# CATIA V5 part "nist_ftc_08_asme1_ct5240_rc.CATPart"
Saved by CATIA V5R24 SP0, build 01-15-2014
Part number: NIST PMI FTC 08 ASME1
Revision: C
Description: NIST PMI test model downloaded from http://go.usa.gov/mGVm
Bounding box of the stored display mesh (mm): x -155.797 to 155.797, y -111.347 to 111.347, z 0 to 48.26
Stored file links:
  C:\work\NIST\DCC_review\nist_ftc_08_asme1_ct5240_rc.CATPart
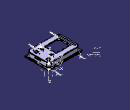
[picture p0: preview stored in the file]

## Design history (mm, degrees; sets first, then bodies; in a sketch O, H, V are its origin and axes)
f4a2d38f3ddc11d3a929006094b99c4b_11 "CATTPSSet"
TTRSSet1
Set1 "MBD_A_GEOM"
  Plane1: type Equation, A 0.57735, B -0.57735, C -0.57735, Length -28.26, RefPoint vertex [face of Fillet7 | start face of Pad1 | face of Pad1 from Sketch5.L4], RefAxis AxisSystem9
Set2
  Point1: type Center, Curve edge [face of Hole1 | start face of Pad1]
  Point2: type OnPlane, Support end face of Pad2, H 142.875, V 98.425, Direction (1, 0, 0)
  Point3: type Center, Curve edge [end face of Pad2 | face of Hole5]
Set3 "MBD_A"
  AxisSystem1 "ABC": origin (142.875, 98.425, 0), X (0, -1, 0), Y (-1, 0, 0), Z (0, 0, -1)
  AxisSystem2 "DBC": origin (142.875, 98.425, 48.26), X (0, 1, 0), Y (-1, 0, 0), Z (0, 0, 1)
Set4 "MBD_B"
  AxisSystem3: origin (142.875, 98.425, 0), X (0, -1, 0), Y (-1, 0, 0), Z (0, 0, -1)
  AxisSystem4: origin (142.875, 98.425, 48.26), X (0, 1, 0), Y (-1, 0, 0), Z (0, 0, 1)
  Sketch1 on face of Pad2 from Sketch6.L3, origin (0, -102.4573, 0), H (1, 0, 0), V (0, 0, 1)
    axis line L1 (0, -16.144) -> (0, 81.9836)
    point P5 (0, -16.144)
    line L2 (50.8, 45.212) -> (50.8, 11.684)
    line L3 (-50.8, 45.212) -> (-50.8, 11.684)
    projected line E4 (121.8957, 11.684) -> (-121.8957, 11.684) from edge [face of Pad2 from Sketch6.L3 | face of Fillet9]
    projected line E5 (50.8, 11.684) -> (-50.8, 11.684) from edge [face of Pad2 from Sketch6.L3 | face of Fillet9]
    distance L1 L2 = 50.8
    distance L1 L3 = 50.8
    coincidence: P5 V
    vertical: L1 V, L2 V, L3 V
  AxisSystem5 "DE-F": origin (-38.1, 0, 48.26), X (0, 1, 0), Y (-1, 0, 0), Z (0, 0, 1)
  Sketch2 on end face of Pad2, origin (0, 0, 48.26), H (1, 0, 0), V (0, 1, 0)
    axis line L1 (-38.1, 55.626) -> (-38.1, -55.626)
    point P1 (-38.1, -55.626)
    point P2 (-38.1, 55.626)
    reference projected point E3 (-38.1, -55.626) from axis of face of RectPattern3
    reference projected point E4 (-38.1, 55.626) from axis of face of RectPattern3
    point P3 (-38.1, 0)
    vertical: L1 V
    coincidence: E3 P1, E4 P2
    midpoint: P3 L1
  Fill1: Boundary Sketch1
Set5 "MBD_C"
  Sketch3 on end face of Pad2, origin (0, 0, 48.26), H (1, 0, 0), V (0, 1, 0)
    axis line L1 (109.22, -20.955) -> (109.22, -78.105)
    point P1 (109.22, -20.955)
    point P2 (109.22, -78.105)
    reference projected point E1 (109.22, -20.955) from axis of face of Hole4
    reference projected point E2 (109.22, -78.105) from axis of face of RectPattern4
    point P3 (109.22, -49.53)
    vertical: L1 V
    coincidence: E1 P1, E2 P2
    midpoint: P3 L1
  AxisSystem6 "DG": origin (109.22, -49.53, 48.26), X (0, 1, 0), Y (-1, 0, 0), Z (0, 0, 1)
  AxisSystem7: origin (142.875, 98.425, 48.26), X (0, 1, 0), Y (-1, 0, 0), Z (0, 0, 1)
Set6 "MBD_D"
  Sketch4 on end face of Pad2, origin (0, 0, 48.26), H (1, 0, 0), V (0, 1, 0)
    axis line L1 (69.85, -25.1263) -> (69.85, -67.31)
    point P2 (69.85, -67.31)
    reference projected point E1 (69.85, -67.31) from axis of face of RectPattern5
    point P3 (69.85, -46.2182)
    vertical: L1 V
    coincidence: E1 P2
    midpoint: P3 L1
  AxisSystem8 "DHJ": origin (69.85, -46.2182, 48.26), X (0, 1, 0), Y (-1, 0, 0), Z (0, 0, 1)
  AxisSystem9 "DKL": origin (69.85, 25.4, 48.26), X (0, 1, 0), Y (-1, 0, 0), Z (0, 0, 1)
  AxisSystem10: origin (142.875, 98.425, 48.26), X (0, 1, 0), Y (-1, 0, 0), Z (0, 0, 1)
Body1 (main body)
  Sketch5 on xy-plane, origin (0, 0, 0), H (1, 0, 0), V (0, 1, 0)
    line L1 (-155.7973, 111.3473) -> (155.7973, 111.3473)
    line L2 (155.7973, 111.3473) -> (155.7973, -111.3473)
    line L3 (155.7973, -111.3473) -> (-155.7973, -111.3473)
    line L4 (-155.7973, -111.3473) -> (-155.7973, 111.3473)
    length L3 = 311.5945
    distance V L4 = 155.7973
    length L2 = 222.6945
    distance H L1 = 111.3473
    horizontal: L1 H, L3 H
    vertical: L2 V, L4 V
  Pad1: profile Sketch5, direction (0, 0, 1), length 10.16
  Sketch6 on end face of Pad1, origin (0, 0, 10.16), H (1, 0, 0), V (0, 1, 0)
    line L1 (-123.1583, 102.4573) -> (123.1583, 102.4573)
    line L2 (146.0183, 79.5973) -> (146.0183, -79.5973)
    line L3 (123.1583, -102.4573) -> (-123.1583, -102.4573)
    line L4 (-146.0183, -79.5973) -> (-146.0183, 79.5973)
    line L5 (123.1583, 102.4573) -> (146.0183, 79.5973)
    line L6 (146.0183, -79.5973) -> (123.1583, -102.4573)
    line L7 (-123.1583, 102.4573) -> (-146.0183, 79.5973)
    point P1 (-142.7555, 82.86)
    line L8 (-146.0183, -79.5973) -> (-123.1583, -102.4573)
    point P2 (-123.1583, 102.4573)
    point P5 (-123.1583, -102.4573)
    point P6 (123.1583, -102.4573)
    point P9 (123.1583, 102.4573)
    reference projected line E1 (-155.7973, 111.3473) -> (-155.7973, -111.3473) from edge [face of Pad1 from Sketch5.L4 | end face of Pad1]
    reference projected line E2 (155.7973, -111.3473) -> (155.7973, 111.3473) from edge [face of Pad1 from Sketch5.L2 | end face of Pad1]
    reference projected line E3 (-155.7973, -111.3473) -> (155.7973, -111.3473) from edge [face of Pad1 from Sketch5.L3 | end face of Pad1]
    reference projected line E4 (155.7973, 111.3473) -> (-155.7973, 111.3473) from edge [face of Pad1 from Sketch5.L1 | end face of Pad1]
    angle L1 L7 = 45
    distance L4 E1 = 9.779
    distance L2 E2 = 9.779
    distance L3 E3 = 8.89
    distance E4 L1 = 8.89
    distance L4 P2 = 22.86
    distance P9 L2 = 22.86
    angle L5 L1 = 45
    distance L2 P6 = 22.86
    angle L3 L6 = 45
    distance P5 L4 = 22.86
    angle L3 L8 = 45
    horizontal: L1 H, L3 H
    vertical: L2 V, L4 V
    coincidence: P1 L7
  Pad2: profile Sketch6, direction (0, 0, 1), length 38.1
  Sketch7 on end face of Pad1, origin (138.8883, 98.2031, 10.16), H (1, 0, 0), V (0, 1, 0)
    point P1 (3.9867, 0.2219)
    reference intersected line E1 through (0, -98.2031) direction (-1, 0) from zx-plane
    reference intersected line E2 through (-138.8883, 0) direction (0, 1) from yz-plane
    distance E1 P1 = 98.425
    distance E2 P1 = 142.875
  Hole1: placed by Sketch7, at (142.875, 98.425, 10.16) direction (0, 0, -1), diameter 6.0325, through (limit type 6)
  RectPattern1: of Hole1, direction 1 instances 2, spacing 285.75, along edge [face of Pad1 from Sketch5.L1 | end face of Pad1], direction 2 instances 2, spacing 196.85, along edge [face of Pad1 from Sketch5.L2 | end face of Pad1] reversed
  Sketch8 on start face of Pad1, origin (0, 0, 0), H (1, 0, 0), V (0, -1, 0)
    line L1 (120.528, 96.1073) -> (139.6683, 76.967)
    line L2 (139.6683, 76.967) -> (139.6683, -76.967)
    line L3 (139.6683, -76.967) -> (120.528, -96.1073)
    line L4 (120.528, -96.1073) -> (-120.528, -96.1073)
    line L5 (-120.528, -96.1073) -> (-139.6683, -76.967)
    line L6 (-139.6683, -76.967) -> (-139.6683, 76.967)
    line L7 (-139.6683, 76.967) -> (-120.528, 96.1073)
    line L8 (-120.528, 96.1073) -> (120.528, 96.1073)
  Pocket1: profile Sketch8, direction (0, 0, 1), length 44.831
  Sketch9 on end face of Pad2, origin (0, 0, 48.26), H (1, 0, 0), V (0, 1, 0)
    point P1 (-107.95, 57.15)
    line L1 (-107.95, 57.15) -> (-90.17, 57.15)
    line L2 (31.75, 57.15) -> (31.75, 33.02)
    line L3 (31.75, -57.15) -> (13.97, -57.15)
    line L4 (-107.95, -57.15) -> (-107.95, -33.02)
    point P3 (31.75, -57.15)
    point P4 (-107.95, -57.15)
    reference intersected line E1 through (0, 0) direction (0, 1) from yz-plane
    reference intersected line E2 through (0, 0) direction (-1, 0) from zx-plane
    arc A1 centre (-106.426, 25.4) radius 7.62 from (-106.426, 17.78) to (-106.426, 33.02) ccw
    point P5 (-106.426, 25.4)
    reference intersected line E3 through (0, 0) direction (-1, 0) from zx-plane
    line L5 (-106.426, 33.02) -> (-107.95, 33.02)
    point P6 (-106.426, 33.02)
    line L6 (-106.426, 17.78) -> (-107.95, 17.78)
    point P7 (-106.426, 17.78)
    point P8 (-107.95, 33.02)
    line L7 (-107.95, 33.02) -> (-107.95, 57.15)
    point P9 (-107.95, 17.78)
    construction line L8 (0, 0) -> (-140, 0)
    point P11 (-107.95, -33.02)
    point P12 (-106.426, -33.02)
    line L9 (-106.426, -33.02) -> (-107.95, -33.02)
    point P13 (-106.426, -17.78)
    arc A2 centre (-106.426, -25.4) radius 7.62 from (-106.426, -17.78) to (-106.426, -33.02) cw
    point P15 (-107.95, -17.78)
    line L10 (-106.426, -17.78) -> (-107.95, -17.78)
    line L11 (-107.95, -17.78) -> (-107.95, 17.78)
    axis line L12 (-38.1, -57.15) -> (-38.1, 57.15)
    point P16 (-38.1, -57.15)
    point P17 (-38.1, 57.15)
    point P18 (30.226, 33.02)
    point P19 (30.226, 17.78)
    arc A3 centre (30.226, 25.4) radius 7.62 from (30.226, 17.78) to (30.226, 33.02) cw
    point P21 (31.75, 17.78)
    line L13 (30.226, 17.78) -> (31.75, 17.78)
    point P22 (31.75, 33.02)
    line L14 (30.226, 33.02) -> (31.75, 33.02)
    point P23 (31.75, -17.78)
    point P24 (30.226, -17.78)
    line L15 (30.226, -17.78) -> (31.75, -17.78)
    point P25 (30.226, -33.02)
    arc A4 centre (30.226, -25.4) radius 7.62 from (30.226, -17.78) to (30.226, -33.02) ccw
    point P27 (31.75, -33.02)
    line L16 (30.226, -33.02) -> (31.75, -33.02)
    line L17 (31.75, 17.78) -> (31.75, -17.78)
    line L18 (31.75, -33.02) -> (31.75, -57.15)
    arc A5 centre (6.35, -55.626) radius 7.62 from (13.97, -55.626) to (-1.27, -55.626) ccw
    point P28 (6.35, -55.626)
    line L19 (13.97, -55.626) -> (13.97, -57.15)
    point P29 (13.97, -55.626)
    line L20 (-1.27, -55.626) -> (-1.27, -57.15)
    point P30 (-1.27, -55.626)
    line L21 (-1.27, -57.15) -> (-30.48, -57.15)
    point P32 (-1.27, -57.15)
    point P33 (-74.93, -57.15)
    point P34 (-74.93, -55.626)
    line L22 (-74.93, -55.626) -> (-74.93, -57.15)
    point P35 (-90.17, -57.15)
    point P36 (-90.17, -55.626)
    line L23 (-90.17, -55.626) -> (-90.17, -57.15)
    arc A6 centre (-82.55, -55.626) radius 7.62 from (-90.17, -55.626) to (-74.93, -55.626) cw
    line L24 (-90.17, -57.15) -> (-107.95, -57.15)
    point P38 (-90.17, 57.15)
    point P39 (-90.17, 55.626)
    line L25 (-90.17, 55.626) -> (-90.17, 57.15)
    point P40 (-74.93, 55.626)
    arc A7 centre (-82.55, 55.626) radius 7.62 from (-90.17, 55.626) to (-74.93, 55.626) ccw
    point P42 (-74.93, 57.15)
    line L26 (-74.93, 55.626) -> (-74.93, 57.15)
    point P43 (-1.27, 57.15)
    point P44 (-1.27, 55.626)
    line L27 (-1.27, 55.626) -> (-1.27, 57.15)
    point P45 (13.97, 55.626)
    arc A8 centre (6.35, 55.626) radius 7.62 from (13.97, 55.626) to (-1.27, 55.626) cw
    line L28 (13.97, 55.626) -> (13.97, 57.15)
    line L29 (13.97, 57.15) -> (31.75, 57.15)
    line L30 (-74.93, 57.15) -> (-45.72, 57.15)
    arc A9 centre (-38.1, -55.626) radius 7.62 from (-30.48, -55.626) to (-45.72, -55.626) ccw
    point P48 (-38.1, -55.626)
    line L31 (-30.48, -55.626) -> (-30.48, -57.15)
    point P49 (-30.48, -55.626)
    line L32 (-45.72, -55.626) -> (-45.72, -57.15)
    point P50 (-45.72, -55.626)
    line L33 (-45.72, -57.15) -> (-74.93, -57.15)
    point P51 (-30.48, -57.15)
    point P52 (-45.72, -57.15)
    point P53 (-45.72, 57.15)
    point P54 (-45.72, 55.626)
    line L34 (-45.72, 55.626) -> (-45.72, 57.15)
    point P55 (-30.48, 55.626)
    arc A10 centre (-38.1, 55.626) radius 7.62 from (-30.48, 55.626) to (-45.72, 55.626) cw
    point P57 (-30.48, 57.15)
    line L35 (-30.48, 55.626) -> (-30.48, 57.15)
    line L36 (-30.48, 57.15) -> (-1.27, 57.15)
    distance L4 E1 = 107.95
    distance E2 L3 = 57.15
    distance P5 L4 = 1.524
    radius A1 = 7.62
    distance E3 P5 = 25.4
    distance P4 P1 = 114.3
    radius A5 = 7.62
    distance L3 P28 = 1.524
    distance P28 L12 = 44.45
    distance P3 P4 = 139.7
    radius A9 = 7.62
    distance L21 P48 = 1.524
    horizontal: L1 H, L3 H, L5 H, L6 H, L8 H, L21 H, L24 H, L29 H, L30 H, L33 H, L36 H
    vertical: L2 V, L4 V, L7 V, L11 V, L12 V, L17 V, L18 V, L20 V, L19 V, L31 V, L32 V
    tangency: L5 A1, L6 A1, L19 A5, L20 A5, L31 A9, L32 A9
    coincidence: L4 P8, L4 L11, L2 L17, L17 L18, L3 P16, L3 L21, L1 P17, L1 L29, P48 L12, L21 L33, L30 L36
    symmetry: P8 P11 L8, P6 P12 L8, L5 L9 L8, P7 P13 L8, A1 A2 L8, P9 P15 L8, L6 L10 L8, P6 P18 L12, P7 P19 L12, A1 A3 L12, P9 P21 L12, L6 L13 L12, P8 P22 L12, L5 L14 L12, P15 P23 L12, P13 P24 L12, L10 L15 L12, P12 P25 L12, A2 A4 L12, P11 P27 L12, L9 L16 L12, P32 P33 L12, P30 P34 L12, L20 L22 L12, P29 P36 L12, L19 L23 L12, A5 A6 L12, P35 P38 L8, P36 P39 L8, L23 L25 L8, P34 P40 L8, A6 A7 L8, P33 P42 L8, L22 L26 L8, P32 P43 L8, P30 P44 L8, L20 L27 L8, P29 P45 L8, A5 A8 L8, L19 L28 L8, P52 P53 L8, P50 P54 L8, L32 L34 L8, P49 P55 L8, A9 A10 L8, P51 P57 L8, L31 L35 L8
  Pocket2: profile Sketch9, direction (0, 0, -1), through (limit type 6)
  Sketch10 on end face of Pad2, origin (-103.9484, 24.3967, 48.26), H (1, 0, 0), V (0, 1, 0)
    point P1 (-2.4776, 1.0033)
    reference projected arc E1 centre (-2.4776, 1.0033) radius 7.62 from (-2.4776, -6.6167) to (-2.4776, 8.6233) ccw from edge [end face of Pad2 | face of Pocket2 from Sketch9.A1]
    concentricity: E1 P1
  Hole2: placed by Sketch10, at (-106.426, 25.4, 48.26) direction (0, 0, -1), diameter 5.4102, through (limit type 6)
  RectPattern2: of Hole2, direction 1 instances 2, spacing 50.8, along edge [end face of Pad2 | face of Pocket2 from Sketch9.L11], direction 2 instances 2, spacing 136.652, along edge [end face of Pad2 | face of Pocket2 from Sketch9.L21]
  Sketch11 on end face of Pad2, origin (-83.348, -53.7047, 48.26), H (1, 0, 0), V (0, 1, 0)
    point P1 (0.798, -1.9213)
    reference projected point E1 (0.798, -1.9213) from axis of face of Pocket2 from Sketch9.A6
    coincidence: E1 P1
  Hole3: placed by Sketch11, at (-82.55, -55.626, 48.26) direction (0, 0, -1), diameter 5.4102, through (limit type 6)
  RectPattern3: of Hole3, direction 1 instances 3, spacing 44.45, along edge [end face of Pad2 | face of Pocket2 from Sketch9.L33], direction 2 instances 2, spacing 111.252, along edge [end face of Pad2 | face of Pocket2 from Sketch9.L11] reversed
  Sketch12 on end face of Pad2, origin (0, 0, 48.26), H (1, 0, 0), V (0, 1, 0)
    line L1 (95.25, -35.56) -> (123.19, -35.56)
    line L2 (123.19, -35.56) -> (123.19, -63.5)
    line L3 (123.19, -63.5) -> (95.25, -63.5)
    line L4 (95.25, -63.5) -> (95.25, -35.56)
    reference intersected line E1 through (0, 0) direction (0, 1) from yz-plane
    reference intersected line E2 through (0, 0) direction (-1, 0) from zx-plane
    length L1 = 27.94
    length L2 = 27.94
    distance E1 L4 = 95.25
    distance E2 L1 = 35.56
    horizontal: L1 H, L3 H
    vertical: L2 V, L4 V
  Pocket3: profile Sketch12, direction (0, 0, -1), through (limit type 6)
  Sketch13 on end face of Pad2, origin (108.1397, -22.5136, 48.26), H (1, 0, 0), V (0, 1, 0)
    point P1 (1.0803, 1.5586)
    reference intersected line E1 through (-108.1397, 0) direction (0, 1) from yz-plane
    reference intersected line E2 through (0, 22.5136) direction (-1, 0) from zx-plane
    distance E1 P1 = 109.22
    distance E2 P1 = 20.955
  Hole4: placed by Sketch13, at (109.22, -20.955, 48.26) direction (0, 0, -1), diameter 6.35, through (limit type 6)
  RectPattern4: of Hole4, direction 1 instances 2, spacing 57.15, along edge [end face of Pad2 | face of Pocket3 from Sketch12.L2] reversed, direction 2 instances 2, spacing 111.252
  Sketch14 on end face of Pad2, origin (96.9796, 25.3434, 48.26), H (1, 0, 0), V (0, 1, 0)
    point P1 (-27.1296, 0.0566)
    reference intersected line E1 through (-96.9796, 0) direction (0, 1) from yz-plane
    reference intersected line E2 through (0, -25.3434) direction (-1, 0) from zx-plane
    distance E1 P1 = 69.85
    distance P1 E2 = 25.4
  Hole5: placed by Sketch14, at (69.85, 25.4, 48.26) direction (0, 0, -1), diameter 5.7912, through (limit type 6)
  RectPattern5: of Hole5, direction 1 instances 2, spacing 92.71, along edge [face of Pad2 from Sketch6.L2 | end face of Pad2] reversed, direction 2 instances 2, spacing 111.252
  Sketch15 on end face of Pad2, origin (70.1334, 59.5545, 48.26), H (1, 0, 0), V (0, 1, 0)
    point P1 (-0.2834, 7.7555)
    reference intersected line E1 through (0, -59.5545) direction (-1, 0) from zx-plane
    reference intersected line E2 through (-70.1334, 0) direction (0, 1) from yz-plane
    distance E1 P1 = 67.31
    distance E2 P1 = 69.85
  Hole6: placed by Sketch15, at (69.85, 67.31, 48.26) direction (0, 0, -1), diameter 6.1468, through (limit type 6)
  RectPattern6: of Hole6, direction 1 instances 2, spacing 92.71, along edge [face of Pad2 from Sketch6.L2 | end face of Pad2] reversed, direction 2 instances 2, spacing 111.252
  Sketch16 on end face of Pad2, origin (0, 0, 48.26), H (1, 0, 0), V (0, 1, 0)
    construction line L1 (50, 46.355) -> (180, 46.355)
    construction line L2 (59.69, 70) -> (59.69, -80)
    reference intersected line E1 through (0, 0) direction (0, 1) from yz-plane
    reference intersected line E2 through (0, 0) direction (-1, 0) from zx-plane
    arc A1 centre (59.69, 54.61) radius 7.62 from (67.31, 54.61) to (52.07, 54.61) ccw
    point P5 (59.69, 54.61)
    arc A2 centre (59.69, 38.1) radius 7.62 from (67.31, 38.1) to (52.07, 38.1) cw
    line L3 (46.99, 52.705) -> (46.99, 40.005)
    line L4 (46.99, 52.705) -> (52.07, 52.705)
    point P7 (46.99, 52.705)
    line L5 (52.07, 54.61) -> (52.07, 52.705)
    line L6 (67.31, 54.61) -> (67.31, 51.435)
    point P8 (67.31, 54.61)
    point P9 (67.31, 38.1)
    arc A3 centre (67.31, 46.355) radius 5.08 from (67.31, 41.275) to (67.31, 51.435) ccw
    point P10 (67.31, 46.355)
    line L7 (67.31, 41.275) -> (67.31, 38.1)
    point P12 (52.312, 52.705)
    point P13 (67.31, 54.61)
    line L8 (46.99, 40.005) -> (52.07, 40.005)
    line L9 (52.07, 38.1) -> (52.07, 40.005)
    axis line L10 (-21.2756, -46.355) -> (171.7584, -46.355)
    reference intersected line E3 through (0, 0) direction (-1, 0) from zx-plane
    arc A4 centre (59.69, -38.1) radius 7.62 from (67.31, -38.1) to (52.07, -38.1) ccw
    point P24 (59.69, -38.1)
    arc A5 centre (59.69, -54.61) radius 7.62 from (52.07, -54.61) to (67.31, -54.61) ccw
    point P25 (59.69, -54.61)
    point P26 (67.31, -54.61)
    arc A6 centre (67.31, -46.355) radius 5.08 from (67.31, -51.435) to (67.31, -41.275) ccw
    point P27 (67.31, -46.355)
    line L11 (67.31, -38.1) -> (67.31, -41.275)
    point P28 (67.31, -38.1)
    line L12 (67.31, -54.61) -> (67.31, -51.435)
    line L13 (52.07, -38.1) -> (52.07, -54.61)
    distance E1 L2 = 59.69
    distance E2 L1 = 46.355
    radius A1 = 7.62
    distance P5 L1 = 8.255
    distance L3 L2 = 12.7
    distance L1 L4 = 6.35
    radius A3 = 5.08
    distance E3 L10 = 46.355
    distance P24 P25 = 16.51
    distance L10 P24 = 8.255
    radius A6 = 5.08
    horizontal: L1 H, L4 H, L10 H
    vertical: L2 V, L3 V, L6 V, L7 V, L5 V, L9 V, L11 V
    coincidence: P5 L2, P7 L3, P8 A1, P9 A2, L6 P10, L6 L7, A1 P12, L6 P13, P12 L4, P24 L2, P25 L2, A5 P26, P26 L6, P27 L10, P28 A4, P27 L11
    symmetry: A1 A2 L1, L4 L8 L1
    tangency: L5 A1, L9 A2, L6 A1, A4 L6, A5 L6, L11 A4, L12 A5, L13 A5
    equidistance: P8 P9 P10
  Pocket4: profile Sketch16, direction (0, 0, -1), through (limit type 6)
  Sketch17 on end face of Pad2, origin (0, 0, 48.26), H (1, 0, 0), V (0, 1, 0)
    line L1 (-130.81, 79.375) -> (-118.11, 79.375)
    line L2 (-118.11, 79.375) -> (-118.11, -79.375)
    line L3 (-118.11, -79.375) -> (-130.81, -79.375)
    line L4 (-130.81, -79.375) -> (-130.81, 79.375)
    reference intersected line E1 through (0, 0) direction (-1, 0) from zx-plane
    reference intersected line E2 through (0, 0) direction (0, 1) from yz-plane
    length L1 = 12.7
    distance E1 L1 = 79.375
    length L4 = 158.75
    distance E2 L2 = 118.11
    horizontal: L1 H, L3 H
    vertical: L2 V, L4 V
  Pocket5: profile Sketch17, direction (0, 0, -1), length 1.27
  Fillet1: radius 3.175, on edge [face of Pocket2 from Sketch9.L24 | face of Pocket2 from Sketch9.L4]; edge [face of Pocket2 from Sketch9.L4 | face of Pocket2 from Sketch9.L9]; edge [face of Pocket2 from Sketch9.L10 | face of Pocket2 from Sketch9.L11]; edge [face of Pocket2 from Sketch9.L11 | face of Pocket2 from Sketch9.L6]; edge [face of Pocket2 from Sketch9.L5 | face of Pocket2 from Sketch9.L7]; edge [face of Pocket2 from Sketch9.L7 | face of Pocket2 from Sketch9.L1]; edge [face of Pocket2 from Sketch9.L1 | face of Pocket2 from Sketch9.L25]; edge [face of Pocket2 from Sketch9.L26 | face of Pocket2 from Sketch9.L30]; edge [face of Pocket2 from Sketch9.L30 | face of Pocket2 from Sketch9.L34]; edge [face of Pocket2 from Sketch9.L35 | face of Pocket2 from Sketch9.L36]; edge [face of Pocket2 from Sketch9.L36 | face of Pocket2 from Sketch9.L27]; edge [face of Pocket2 from Sketch9.L28 | face of Pocket2 from Sketch9.L29]; edge [face of Pocket2 from Sketch9.L29 | face of Pocket2 from Sketch9.L2]; edge [face of Pocket2 from Sketch9.L2 | face of Pocket2 from Sketch9.L14]; edge [face of Pocket2 from Sketch9.L13 | face of Pocket2 from Sketch9.L17]; edge [face of Pocket2 from Sketch9.L17 | face of Pocket2 from Sketch9.L15]; edge [face of Pocket2 from Sketch9.L16 | face of Pocket2 from Sketch9.L18]; edge [face of Pocket2 from Sketch9.L18 | face of Pocket2 from Sketch9.L3]; edge [face of Pocket2 from Sketch9.L3 | face of Pocket2 from Sketch9.L19]; edge [face of Pocket2 from Sketch9.L20 | face of Pocket2 from Sketch9.L21]; edge [face of Pocket2 from Sketch9.L21 | face of Pocket2 from Sketch9.L31]; edge [face of Pocket2 from Sketch9.L32 | face of Pocket2 from Sketch9.L33]; edge [face of Pocket2 from Sketch9.L33 | face of Pocket2 from Sketch9.L22]; edge [face of Pocket2 from Sketch9.L23 | face of Pocket2 from Sketch9.L24]
  Fillet2: radius 3.175, on edge [face of Pocket5 from Sketch17.L3 | face of Pocket5 from Sketch17.L4]; edge [face of Pocket5 from Sketch17.L2 | face of Pocket5 from Sketch17.L3]; edge [face of Pocket5 from Sketch17.L4 | face of Pocket5 from Sketch17.L1]; edge [face of Pocket5 from Sketch17.L1 | face of Pocket5 from Sketch17.L2]
  Fillet3: radius 0.762, on edge [face of Pocket5 from Sketch17.L4 | end face of Pocket5]
  Fillet4: radius 1.5875, on edge [face of Pocket4 from Sketch16.L8 | face of Pocket4 from Sketch16.L3]; edge [face of Pocket4 from Sketch16.L3 | face of Pocket4 from Sketch16.L4]
  Fillet5: radius 1.5875, on edge [face of Pocket3 from Sketch12.L3 | face of Pocket3 from Sketch12.L4]; edge [face of Pocket3 from Sketch12.L4 | face of Pocket3 from Sketch12.L1]; edge [face of Pocket3 from Sketch12.L1 | face of Pocket3 from Sketch12.L2]; edge [face of Pocket3 from Sketch12.L2 | face of Pocket3 from Sketch12.L3]
  Fillet6: radius 3.048, on edge [face of Pad2 from Sketch6.L4 | face of Pad2 from Sketch6.L7]; edge [face of Pad2 from Sketch6.L7 | end face of Pad2]; edge [face of Pad2 from Sketch6.L4 | end face of Pad2]; edge [face of Pad2 from Sketch6.L8 | face of Pad2 from Sketch6.L4]; edge [face of Pad2 from Sketch6.L8 | end face of Pad2]; edge [face of Pad2 from Sketch6.L3 | face of Pad2 from Sketch6.L8]; edge [face of Pad2 from Sketch6.L3 | end face of Pad2]; edge [face of Pad2 from Sketch6.L6 | face of Pad2 from Sketch6.L3]; edge [face of Pad2 from Sketch6.L6 | end face of Pad2]; edge [face of Pad2 from Sketch6.L2 | face of Pad2 from Sketch6.L6]; edge [face of Pad2 from Sketch6.L2 | end face of Pad2]; edge [face of Pad2 from Sketch6.L5 | face of Pad2 from Sketch6.L2]; edge [face of Pad2 from Sketch6.L5 | end face of Pad2]; edge [face of Pad2 from Sketch6.L1 | face of Pad2 from Sketch6.L5]; edge [face of Pad2 from Sketch6.L1 | end face of Pad2]; edge [face of Pad2 from Sketch6.L7 | face of Pad2 from Sketch6.L1]
  Fillet7: radius 3.048, on edge [face of Pad1 from Sketch5.L1 | face of Pad1 from Sketch5.L2]; edge [face of Pad1 from Sketch5.L1 | end face of Pad1]; edge [face of Pad1 from Sketch5.L2 | end face of Pad1]; edge [face of Pad1 from Sketch5.L4 | face of Pad1 from Sketch5.L1]; edge [face of Pad1 from Sketch5.L4 | end face of Pad1]; edge [face of Pad1 from Sketch5.L3 | face of Pad1 from Sketch5.L4]; edge [face of Pad1 from Sketch5.L3 | end face of Pad1]; edge [face of Pad1 from Sketch5.L2 | face of Pad1 from Sketch5.L3]
  Fillet8: radius 3.048, on edge [face of Pocket1 from Sketch8.L8 | face of Pocket1 from Sketch8.L1]; edge [face of Pocket1 from Sketch8.L8 | end face of Pocket1]; edge [face of Pocket1 from Sketch8.L1 | end face of Pocket1]; edge [face of Pocket1 from Sketch8.L7 | face of Pocket1 from Sketch8.L8]; edge [face of Pocket1 from Sketch8.L7 | end face of Pocket1]; edge [face of Pocket1 from Sketch8.L6 | face of Pocket1 from Sketch8.L7]; edge [face of Pocket1 from Sketch8.L6 | end face of Pocket1]; edge [face of Pocket1 from Sketch8.L5 | face of Pocket1 from Sketch8.L6]; edge [face of Pocket1 from Sketch8.L5 | end face of Pocket1]; edge [face of Pocket1 from Sketch8.L4 | face of Pocket1 from Sketch8.L5]; edge [face of Pocket1 from Sketch8.L4 | end face of Pocket1]; edge [face of Pocket1 from Sketch8.L3 | end face of Pocket1]; edge [face of Pocket1 from Sketch8.L3 | face of Pocket1 from Sketch8.L4]; edge [face of Pocket1 from Sketch8.L2 | end face of Pocket1]; edge [face of Pocket1 from Sketch8.L2 | face of Pocket1 from Sketch8.L3]; edge [face of Pocket1 from Sketch8.L1 | face of Pocket1 from Sketch8.L2]
  Sketch18 on end face of Pad2, origin (103.8066, 57.5041, 48.26), H (1, 0, 0), V (0, 1, 0)
    point P1 (7.9534, 5.9959)
    reference intersected line E1 through (0, -57.5041) direction (-1, 0) from zx-plane
    reference intersected line E2 through (-103.8066, 0) direction (0, 1) from yz-plane
    distance E1 P1 = 63.5
    distance E2 P1 = 111.76
  Hole7: placed by Sketch18, at (111.76, 63.5, 48.26) direction (0, 0, -1), diameter 30.5587, through (limit type 6)
  Sketch19 on end face of Pad2, origin (92.1729, 62.3356, 48.26), H (1, 0, 0), V (0, 1, 0)
    point P1 (5.2996, 1.1644)
    reference intersected line E1 through (0, -62.3356) direction (-1, 0) from zx-plane
    reference intersected line E2 through (-92.1729, 0) direction (0, 1) from yz-plane
    distance E1 P1 = 63.5
    distance E2 P1 = 97.4725
  Hole8: placed by Sketch19, at (97.4725, 63.5, 48.26) direction (0, 0, -1), diameter 6.35, through (limit type 6)
  Sketch20 on end face of Pad2, origin (0, 0, 48.26), H (1, 0, 0), V (0, 1, 0)
    axis line L1 (-38.1, 55.626) -> (-38.1, -55.626)
    point P1 (-38.1, -55.626)
    point P2 (-38.1, 55.626)
    reference projected point E3 (-38.1, -55.626) from axis of face of RectPattern3
    reference projected point E4 (-38.1, 55.626) from axis of face of RectPattern3
    point P3 (-38.1, 0)
    vertical: L1 V
    coincidence: E3 P1, E4 P2
    midpoint: P3 L1
  Fillet9: radius 1.524, on edge [end face of Pad1 | face of Pad2 from Sketch6.L3]
  Sketch21 "Main View" on face of Pad2 from Sketch6.L2, origin (146.0183, 0, 0), H (0, 1, 0), V (0, 0, 1)
    line L1 (-6.1589, 40.4) -> (-6.1589, 29.5957)
    arc A1 centre (-1.9632, 29.5957) radius 4.1957 from (-6.1589, 29.5957) to (-1.9632, 25.4) ccw
    line L2 (-1.9632, 25.4) -> (13.2373, 25.4)
    arc A2 centre (12.5189, 29.9115) radius 4.5683 from (13.2373, 25.4) to (13.2373, 34.4229) ccw
    line L3 (13.2373, 34.4229) -> (3.6106, 34.4229)
    arc A3 centre (3.6106, 35.8333) radius 1.4104 from (3.7255, 37.239) to (3.6106, 34.4229) ccw
    line L4 (3.7255, 37.239) -> (19.4156, 37.239)
    line L5 (19.4156, 37.239) -> (19.4156, 25.4)
    line L6 (19.4156, 25.4) -> (22.5181, 25.4)
    line L7 (22.5181, 25.4) -> (22.5181, 37.239)
    line L8 (22.5181, 37.239) -> (28.9274, 37.239)
    line L9 (28.9274, 37.239) -> (28.9274, 40.4)
    line L10 (28.9274, 40.4) -> (3.3241, 40.4)
    arc A4 centre (3.3241, 35.8533) radius 4.5467 from (3.3241, 40.4) to (3.6681, 31.3196) ccw
    line L11 (3.6681, 31.3196) -> (12.7199, 31.3196)
    arc A5 centre (12.5972, 29.9083) radius 1.4166 from (12.7774, 28.5032) to (12.7199, 31.3196) ccw
    line L12 (12.7774, 28.5032) -> (-1.9341, 28.5032)
    line L13 (-3.0266, 29.5957) -> (-3.0266, 40.4)
    line L14 (-3.0266, 40.4) -> (-6.1589, 40.4)
    line L15 (-27.94, 25.4) -> (-27.94, 37.5621)
    arc A6 centre (-24.679, 37.5621) radius 3.261 from (-22.2848, 39.7761) to (-27.94, 37.5621) ccw
    line L16 (-22.2848, 39.7761) -> (-12.02, 28.6757)
    arc A7 centre (-11.7155, 28.9572) radius 0.4146 from (-12.02, 28.6757) to (-11.3023, 28.9919) ccw
    line L17 (-11.3023, 28.9919) -> (-11.3023, 40.4)
    line L18 (-11.3023, 40.4) -> (-8.1701, 40.4)
    line L19 (-8.1701, 40.4) -> (-8.1701, 28.9171)
    line L20 (-14.4332, 26.7194) -> (-23.9003, 37.009)
    arc A8 centre (-24.2976, 36.6435) radius 0.5399 from (-23.9003, 37.009) to (-24.8375, 36.6435) ccw
    line L21 (-24.8375, 36.6435) -> (-24.8375, 25.4)
    line L22 (-24.8375, 25.4) -> (-27.94, 25.4)
    arc A9 centre (-1.9341, 29.5957) radius 1.0926 from (-3.0266, 29.5957) to (-1.9341, 28.5032) ccw
    arc A10 centre (-11.6872, 28.9171) radius 3.5171 from (-14.4332, 26.7194) to (-8.1701, 28.9171) ccw
  Pocket6: profile Sketch21, direction (-1, 0, 0), length 2.54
